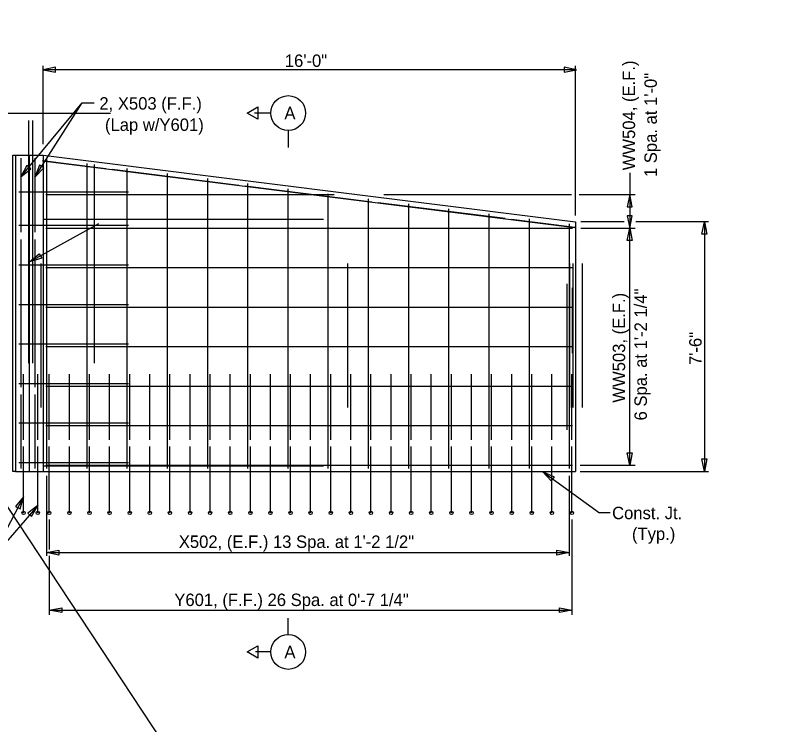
# Model space of a CAD drawing. Extents: x -1609 to 1184, y -412 to 394.
# Drawn here: x -886.43 to -863.11, y -128.08 to -106.77 of the extents above; entities that cross this region are included whole.
import ezdxf

# ---------------------------------------------------------------- set-up
doc = ezdxf.new("R2010")
doc.units = 0
for name, color, linetype in [('DR_P_Culvert', 7, 'Continuous'), ('DR_P_Headwall', 7, 'Continuous'), ('ST_Details', 7, 'Continuous'), ('ST_Text', 7, 'Continuous'), ('XS_P_Finished_Grade', 7, 'Continuous')]:
    doc.layers.add(name, color=color, linetype=linetype)

msp = doc.modelspace()

# ---------------------------------------------------------------- linework, layer by layer
at = {"layer": 'DR_P_Culvert'}
msp.add_line((-892.491, -109.705), (-883.575, -109.705), dxfattribs=at)
msp.add_lwpolyline([(-886.51, -110.974), (-886.425, -110.974), (-886.425, -120.474), (-886.51, -120.474)], close=True, dxfattribs=at)
at = {"layer": 'DR_P_Headwall'}
for p, q in [((-886.425, -110.974), (-885.597, -110.974)), ((-886.011, -110.974), (-886.011, -120.474)), ((-885.597, -110.974), (-869.598, -112.974)), ((-885.597, -110.974), (-885.597, -120.474)), ((-869.598, -112.974), (-869.598, -120.474))]:
    msp.add_line(p, q, dxfattribs=at)
for points in [[(-886.264, -111.058), (-886.264, -113.28)], [(-885.841, -111.058), (-885.841, -113.28)], [(-886.264, -113.502), (-886.264, -117.947)], [(-885.841, -113.502), (-885.841, -117.947)], [(-886.264, -118.169), (-886.264, -120.391)], [(-885.841, -118.169), (-885.841, -120.391)]]:
    msp.add_lwpolyline(points, dxfattribs=at)
at = {"layer": 'ST_Details'}
for p, q in [((-886.035, -109.925), (-886.035, -117.224)), ((-885.919, -109.925), (-885.919, -117.224)), ((-885.618, -111.14), (-869.619, -113.14)), ((-885.493, -111.058), (-885.493, -120.391)), ((-884.285, -111.222), (-884.285, -120.391)), ((-884.066, -111.25), (-884.066, -117.224)), ((-883.077, -111.373), (-883.077, -120.391)), ((-881.868, -111.524), (-881.868, -120.391)), ((-880.66, -111.675), (-880.66, -120.391)), ((-879.452, -111.826), (-879.452, -120.391)), ((-886.322, -112.068), (-883.025, -112.068)), ((-885.514, -112.152), (-876.851, -112.152)), ((-878.243, -111.977), (-878.243, -120.391)), ((-877.035, -112.128), (-877.035, -120.391)), ((-875.827, -112.279), (-875.827, -120.391)), ((-874.618, -112.431), (-874.618, -120.391)), ((-873.41, -112.582), (-873.41, -120.391)), ((-872.202, -112.733), (-872.202, -120.391)), ((-886.322, -113.079), (-883.025, -113.079)), ((-885.588, -112.891), (-877.171, -112.891)), ((-870.993, -112.884), (-870.993, -120.391)), ((-869.785, -113.035), (-869.785, -120.391)), ((-885.514, -113.163), (-869.691, -113.163)), ((-886.322, -114.267), (-883.025, -114.267)), ((-885.667, -114.224), (-885.667, -118.557)), ((-876.448, -114.224), (-876.448, -118.557)), ((-869.774, -114.224), (-869.774, -118.557)), ((-869.674, -114.224), (-869.674, -118.557)), ((-869.394, -114.224), (-869.394, -118.557)), ((-885.514, -114.35), (-869.691, -114.35)), ((-869.857, -114.837), (-869.857, -119.224)), ((-869.701, -114.955), (-869.701, -116.925)), ((-886.322, -115.454), (-883.025, -115.454)), ((-885.514, -115.538), (-869.691, -115.538)), ((-886.322, -116.642), (-883.025, -116.642)), ((-885.514, -116.725), (-869.691, -116.725)), ((-886.181, -119.524), (-886.181, -117.557)), ((-885.758, -119.524), (-885.758, -117.557)), ((-885.41, -119.524), (-885.41, -117.558)), ((-884.806, -119.524), (-884.806, -117.558)), ((-884.202, -119.524), (-884.202, -117.558)), ((-883.597, -119.524), (-883.597, -117.558)), ((-882.993, -119.524), (-882.993, -117.558)), ((-882.389, -119.524), (-882.389, -117.558)), ((-881.785, -119.524), (-881.785, -117.558)), ((-881.181, -119.524), (-881.181, -117.558)), ((-880.577, -119.524), (-880.577, -117.558)), ((-879.972, -119.524), (-879.972, -117.558)), ((-879.368, -119.524), (-879.368, -117.558)), ((-878.764, -119.524), (-878.764, -117.558)), ((-878.16, -119.524), (-878.16, -117.558)), ((-877.556, -119.524), (-877.556, -117.558)), ((-876.952, -119.524), (-876.952, -117.558)), ((-876.347, -119.524), (-876.347, -117.558)), ((-875.743, -119.524), (-875.743, -117.558)), ((-875.139, -119.524), (-875.139, -117.558)), ((-874.535, -119.524), (-874.535, -117.558)), ((-873.931, -119.524), (-873.931, -117.558)), ((-873.327, -119.524), (-873.327, -117.558)), ((-872.722, -119.524), (-872.722, -117.558)), ((-872.118, -119.524), (-872.118, -117.558)), ((-871.514, -119.524), (-871.514, -117.558)), ((-870.91, -119.524), (-870.91, -117.558)), ((-870.306, -119.524), (-870.306, -117.558)), ((-869.702, -119.524), (-869.702, -117.558)), ((-886.322, -117.829), (-883.025, -117.829)), ((-885.514, -117.913), (-869.691, -117.913)), ((-886.322, -119.017), (-883.025, -119.017)), ((-885.514, -119.1), (-869.691, -119.1)), ((-886.322, -120.204), (-883.025, -120.204)), ((-885.588, -120.308), (-877.171, -120.308)), ((-885.514, -120.288), (-869.691, -120.288)), ((-886.425, -120.474), (-869.598, -120.474))]:
    msp.add_line(p, q, dxfattribs=at)
for points in [[(-883.713, -111.378), (-885.618, -111.14)], [(-879.714, -111.878), (-883.523, -111.402)], [(-877.619, -112.14), (-879.523, -111.902)], [(-875.714, -112.378), (-877.618, -112.14)], [(-871.714, -112.878), (-875.523, -112.402)], [(-869.619, -113.14), (-871.524, -112.902)], [(-886.181, -121.724), (-886.181, -119.724)], [(-885.758, -121.724), (-885.758, -119.724)], [(-885.41, -121.724), (-885.41, -119.724)], [(-884.806, -121.724), (-884.806, -119.724)], [(-884.202, -121.724), (-884.202, -119.724)], [(-883.597, -121.724), (-883.597, -119.724)], [(-882.993, -121.724), (-882.993, -119.724)], [(-882.389, -121.724), (-882.389, -119.724)], [(-881.785, -121.724), (-881.785, -119.724)], [(-881.181, -121.724), (-881.181, -119.724)], [(-880.577, -121.724), (-880.577, -119.724)], [(-879.972, -121.724), (-879.972, -119.724)], [(-879.368, -121.724), (-879.368, -119.724)], [(-878.764, -121.724), (-878.764, -119.724)], [(-878.16, -121.724), (-878.16, -119.724)], [(-877.556, -121.724), (-877.556, -119.724)], [(-876.952, -121.724), (-876.952, -119.724)], [(-876.347, -121.724), (-876.347, -119.724)], [(-875.743, -121.724), (-875.743, -119.724)], [(-875.139, -121.724), (-875.139, -119.724)], [(-874.535, -121.724), (-874.535, -119.724)], [(-873.931, -121.724), (-873.931, -119.724)], [(-873.327, -121.724), (-873.327, -119.724)], [(-872.722, -121.724), (-872.722, -119.724)], [(-872.118, -121.724), (-872.118, -119.724)], [(-871.514, -121.724), (-871.514, -119.724)], [(-870.91, -121.724), (-870.91, -119.724)], [(-870.306, -121.724), (-870.306, -119.724)], [(-869.702, -121.724), (-869.702, -119.724)]]:
    msp.add_lwpolyline(points, dxfattribs=at)
msp.add_lwpolyline([(-879.465, -125.904), (-879.141, -125.717), (-879.141, -126.091)], close=True, dxfattribs=at)
for centre in [(-886.181, -121.724), (-885.758, -121.724), (-885.41, -121.725), (-884.806, -121.725), (-884.202, -121.725), (-883.597, -121.725), (-882.993, -121.725), (-882.389, -121.725), (-881.785, -121.725), (-881.181, -121.725), (-880.577, -121.725), (-879.972, -121.725), (-879.368, -121.725), (-878.764, -121.725), (-878.16, -121.725), (-877.556, -121.725), (-876.952, -121.725), (-876.347, -121.725), (-875.743, -121.725), (-875.139, -121.725), (-874.535, -121.725), (-873.931, -121.725), (-873.327, -121.725), (-872.722, -121.725), (-872.118, -121.725), (-871.514, -121.725), (-870.91, -121.725), (-870.306, -121.725), (-869.702, -121.725)]:
    msp.add_circle(centre, 0.0502, dxfattribs=at)
at = {"layer": 'ST_Text'}
for p, q in [((-885.597, -110.637), (-885.597, -108.283)), ((-869.568, -108.402), (-885.597, -108.402)), ((-869.598, -112.787), (-869.598, -108.283)), ((-886.264, -111.618), (-884.423, -109.395)), ((-885.841, -111.627), (-884.423, -109.395)), ((-884.423, -109.395), (-884.066, -109.395)), ((-878.75, -109.703), (-879.245, -109.703)), ((-878.228, -110.225), (-878.228, -110.74)), ((-867.964, -111.501), (-867.964, -112.152)), ((-875.357, -112.152), (-869.717, -112.152)), ((-869.482, -112.152), (-867.801, -112.152)), ((-867.964, -112.152), (-867.964, -113.163)), ((-886.002, -114.178), (-883.925, -113.027)), ((-868.137, -112.974), (-869.439, -112.974)), ((-865.601, -112.974), (-867.781, -112.974)), ((-865.721, -112.974), (-865.721, -120.474)), ((-869.439, -113.163), (-867.801, -113.163)), ((-867.964, -120.288), (-867.964, -113.163)), ((-869.458, -120.288), (-867.801, -120.288)), ((-870.584, -120.474), (-868.872, -121.725)), ((-869.458, -120.474), (-865.601, -120.474)), ((-885.493, -120.614), (-885.493, -123.017)), ((-869.785, -120.61), (-869.785, -123.017)), ((-886.181, -121.239), (-887.191, -123.16)), ((-885.758, -121.497), (-887.191, -123.16)), ((-868.551, -121.725), (-868.872, -121.725)), ((-885.41, -121.921), (-885.41, -122.82)), ((-869.702, -121.921), (-869.702, -124.784)), ((-885.493, -122.915), (-869.785, -122.915)), ((-885.41, -123.017), (-885.41, -124.784)), ((-885.41, -124.647), (-869.702, -124.647)), ((-878.228, -125.382), (-878.228, -124.892)), ((-878.75, -125.904), (-879.215, -125.904))]:
    msp.add_line(p, q, dxfattribs=at)
for points in [[(-885.224, -108.327), (-885.597, -108.402), (-885.224, -108.477)], [(-869.941, -108.477), (-869.568, -108.402), (-869.941, -108.327)], [(-879.465, -109.703), (-879.141, -109.516), (-879.141, -109.89)], [(-886.083, -111.283), (-886.264, -111.618), (-885.968, -111.379)], [(-885.703, -111.272), (-885.841, -111.627), (-885.577, -111.352)], [(-867.89, -112.525), (-867.964, -112.152), (-868.039, -112.525)], [(-868.039, -112.789), (-867.964, -113.163), (-867.89, -112.789)], [(-865.795, -113.348), (-865.721, -112.974), (-865.646, -113.348)], [(-868.039, -113.536), (-867.964, -113.163), (-867.89, -113.536)], [(-885.639, -114.063), (-886.002, -114.178), (-885.711, -113.932)], [(-867.89, -119.914), (-867.964, -120.288), (-868.039, -119.914)], [(-865.646, -120.101), (-865.721, -120.474), (-865.795, -120.101)], [(-870.328, -120.757), (-870.584, -120.474), (-870.239, -120.637)], [(-886.289, -121.605), (-886.181, -121.239), (-886.421, -121.535)], [(-885.945, -121.829), (-885.758, -121.497), (-886.058, -121.731)], [(-885.12, -122.99), (-885.493, -122.915), (-885.12, -122.841)], [(-870.158, -122.841), (-869.785, -122.915), (-870.158, -122.99)], [(-885.037, -124.722), (-885.41, -124.647), (-885.037, -124.573)], [(-870.075, -124.573), (-869.702, -124.647), (-870.075, -124.722)]]:
    msp.add_lwpolyline(points, close=True, dxfattribs=at)
for centre in [(-878.228, -109.703), (-878.228, -125.904)]:
    msp.add_circle(centre, 0.522, dxfattribs=at)
at = {"layer": 'XS_P_Finished_Grade'}
msp.add_line((-939.837, -41.027), (-779.811, -283.389), dxfattribs=at)

# ---------------------------------------------------------------- texts
at = {"layer": 'ST_Text'}
for s, height, p in [('16\'-0"', 0.3733, (-878.332, -108.317)), ('2, X503 (F.F.)', 0.37335, (-883.905, -109.601)), ('A', 0.373, (-878.344, -109.89)), ('(Lap w/Y601)', 0.37335, (-883.737, -110.241)), ('Const. Jt.', 0.3733, (-868.496, -121.912)), ('(Typ.)', 0.3733, (-867.899, -122.539)), ('X502, (E.F.) 13 Spa. at 1\'-2 1/2"', 0.37335, (-881.518, -122.776)), ('Y601, (F.F.) 26 Spa. at 0\'-7 1/4"', 0.37335, (-881.653, -124.523)), ('A', 0.373, (-878.344, -126.091))]:
    msp.add_text(s, height=height, dxfattribs=at).set_placement(p)
for s, height, p in [('WW504, (E.F.)', 0.37335, (-867.805, -111.425)), ('1 Spa. at 1\'-0"', 0.37335, (-867.151, -111.628)), ('WW503, (E.F.)', 0.37335, (-868.104, -118.41)), ('6 Spa. at 1\'-2 1/4"', 0.37335, (-867.451, -118.944)), ('7\'-6"', 0.3733, (-865.806, -117.278))]:
    msp.add_text(s, height=height, rotation=90, dxfattribs=at).set_placement(p)

doc.saveas('drawing.dxf')
